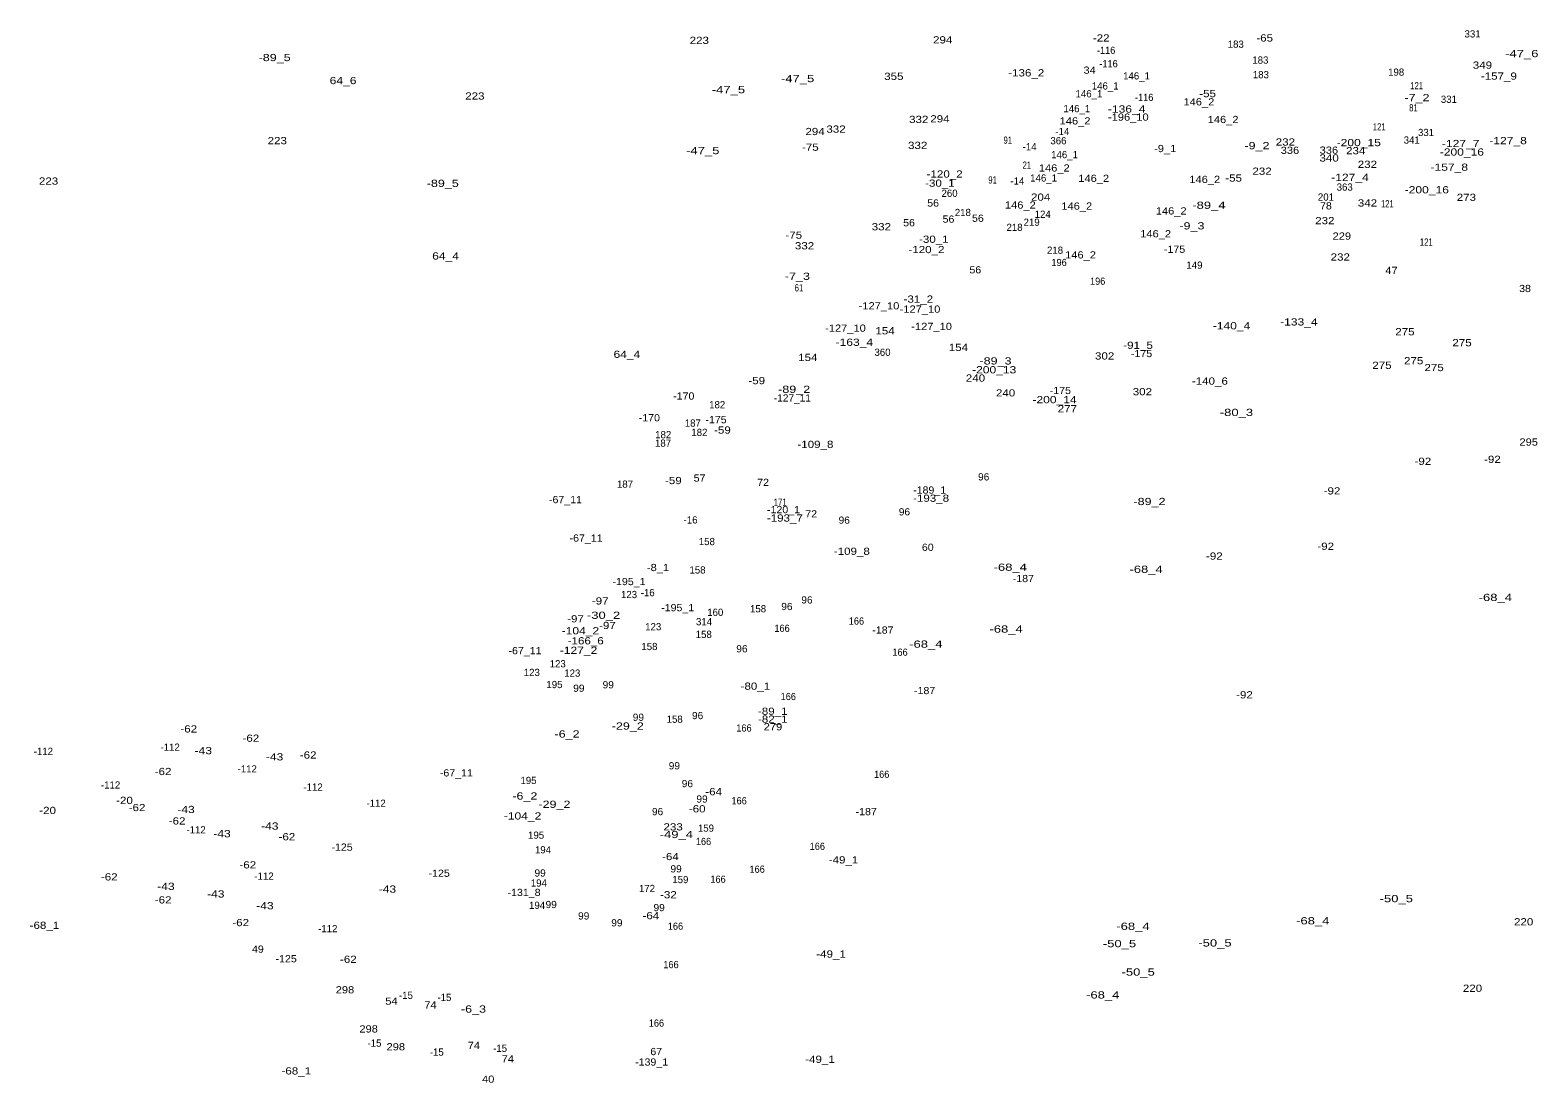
# Model space of a CAD drawing. Extents: x -662996 to -659766, y -998554 to -993949.
# Drawn here: x -661834 to -660997, y -995683 to -995099 of the extents above; entities that cross this region are included whole.
import ezdxf
from ezdxf.enums import TextEntityAlignment as Align

# ---------------------------------------------------------------- set-up
doc = ezdxf.new("R2010")
doc.units = 0
doc.header["$LTSCALE"] = 1.6
doc.layers.add('24', color=7, linetype='Continuous')

msp = doc.modelspace()

# ---------------------------------------------------------------- texts
at = {"layer": '24'}
for s, width, p in [('-22', 1.2, (-661239.28, -995105.72)), ('-65', 1.2, (-661148.56, -995105.71)), ('223', 1.2, (-661462.29, -995107.05)), ('294', 1.2, (-661327.24, -995106.76)), ('-116', 0.95, (-661236.54, -995112.58)), ('-47_6', 1.35, (-661005.9, -995114.38)), ('-89_5', 1.3, (-661697.94, -995116.57)), ('-116', 0.95, (-661235.21, -995120)), ('349', 1.2, (-661027.74, -995120.78)), ('64_6', 1.25, (-661659.97, -995129.36)), ('-47_5', 1.35, (-661407.74, -995128.25)), ('355', 1.2, (-661354.34, -995127)), ('-136_2', 1.2, (-661280.861, -995125.06)), ('34', 1.15, (-661245.709, -995123.58)), ('-157_9', 1.2, (-661018.62, -995126.87)), ('223', 1.2, (-661586.819, -995137.91)), ('-47_5', 1.35, (-661446.11, -995134.39)), ('-116', 0.95, (-661215.42, -995138.67)), ('-55', 1.2, (-661180.25, -995136.59)), ('-7_2', 1.3, (-661064.08, -995138.81)), ('121', 0.8, (-661064.25, -995132.18)), ('-136_4', 1.25, (-661225.15, -995145.14)), ('146_2', 1.15, (-661185.069, -995141.15)), ('81', 0.8, (-661065.98, -995144.45)), ('332', 1.2, (-661386.419, -995156.28)), ('332', 1.2, (-661340.53, -995150.9)), ('294', 1.2, (-661328.76, -995150.57)), ('146_2', 1.15, (-661253.799, -995151.72)), ('-196_10', 1.15, (-661224.23, -995149.6)), ('146_2', 1.15, (-661171.63, -995150.95)), ('121', 0.8, (-661084.98, -995155.04)), ('223', 1.2, (-661696.49, -995162.67)), ('294', 1.2, (-661398.07, -995157.62)), ('91', 0.8, (-661291.101, -995162.4)), ('232', 1.2, (-661137.069, -995163.43)), ('-200_15', 1.25, (-661096.36, -995163.76)), ('-127_7', 1.25, (-661039.78, -995164.27)), ('-127_8', 1.25, (-661013.5, -995162.65)), ('-47_5', 1.35, (-661460.35, -995168.2)), ('-75', 1.2, (-661400.671, -995166.3)), ('332', 1.2, (-661341.1, -995165.31)), ('-9_1', 1.15, (-661203.76, -995167.06)), ('-9_2', 1.3, (-661152.84, -995165.47)), ('336', 1.15, (-661134.55, -995168.04)), ('340', 1.2, (-661112.809, -995172.29)), ('336', 1.15, (-661112.95, -995167.95)), ('234', 1.2, (-661098.04, -995168.24)), ('-200_16', 1.25, (-661039.13, -995168.99)), ('-120_2', 1.2, (-661326.16, -995181.19)), ('21', 0.8, (-661280.54, -995176.26)), ('146_2', 1.15, (-661265.319, -995177.84)), ('232', 1.2, (-661150.02, -995179.62)), ('232', 1.2, (-661091.569, -995175.81)), ('-157_8', 1.25, (-661046.13, -995177.4)), ('223', 1.2, (-661823.38, -995185.11)), ('-89_5', 1.3, (-661604.65, -995186.37)), ('-30_1', 1.2, (-661328.79, -995186.26)), ('91', 0.8, (-661299.551, -995184.49)), ('146_2', 1.15, (-661243.429, -995183.6)), ('146_2', 1.15, (-661181.799, -995184.18)), ('-55', 1.2, (-661165.78, -995183.44)), ('-127_4', 1.25, (-661101.22, -995183.05)), ('-200_16', 1.25, (-661058.611, -995189.93)), ('56', 1.1, (-661332.56, -995197.27)), ('204', 1.2, (-661272.89, -995194.01)), ('342', 1.2, (-661091.53, -995197.24)), ('121', 0.8, (-661080.48, -995197.7)), ('273', 1.2, (-661036.64, -995194.14)), ('56', 1.1, (-661324.02, -995206.2)), ('56', 1.1, (-661307.7, -995205.72)), ('146_2', 1.15, (-661284.14, -995198.39)), ('146_2', 1.15, (-661252.84, -995198.97)), ('146_2', 1.15, (-661200.429, -995201.66)), ('-89_4', 1.35, (-661179.51, -995198.51)), ('78', 1.1, (-661114.58, -995198.85)), ('332', 1.2, (-661361.26, -995210.44)), ('56', 1.1, (-661345.91, -995208.22)), ('146_2', 1.15, (-661209.069, -995214.34)), ('-9_3', 1.3, (-661188.94, -995209.95)), ('232', 1.2, (-661115.179, -995207.05)), ('-75', 1.2, (-661409.88, -995215.09)), ('332', 1.2, (-661403.89, -995221.01)), ('-120_2', 1.2, (-661336.25, -995223.1)), ('-30_1', 1.2, (-661332.15, -995217.37)), ('-175', 1.1, (-661198.56, -995222.94)), ('229', 1.15, (-661105.75, -995215.62)), ('121', 0.8, (-661058.87, -995218.93)), ('64_4', 1.25, (-661603.07, -995226.66)), ('196', 0.95, (-661262.65, -995230.26)), ('146_2', 1.15, (-661250.73, -995226.05)), ('232', 1.2, (-661106.61, -995227.24)), ('-7_3', 1.3, (-661407.85, -995237.92)), ('56', 1.1, (-661309.14, -995234.34)), ('47', 1.15, (-661078.2, -995234.66)), ('61', 0.8, (-661407.01, -995244.35)), ('196', 0.95, (-661241.24, -995240.63)), ('38', 1.1, (-661004.1, -995244.7)), ('-127_10', 1.15, (-661362.571, -995254.31)), ('-127_10', 1.15, (-661339.821, -995256.14)), ('-31_2', 1.2, (-661340.73, -995250.58)), ('-133_4', 1.25, (-661129.59, -995263.24)), ('-127_10', 1.15, (-661381.191, -995266.69)), ('154 ', 1.2, (-661358.35, -995268.16)), ('-127_10', 1.15, (-661333.38, -995265.74)), ('-140_4', 1.25, (-661166.95, -995265.37)), ('275', 1.2, (-661070.74, -995268.67)), ('64_4', 1.25, (-661502.46, -995281.21)), ('-163_4', 1.25, (-661376.25, -995274.52)), ('154 ', 1.2, (-661317.64, -995277.38)), ('-91_5', 1.2, (-661218.811, -995276.2)), ('-175', 1.1, (-661216.89, -995280.79)), ('275', 1.2, (-661039.04, -995274.76)), ('154 ', 1.2, (-661401.17, -995282.95)), ('-200_13', 1.25, (-661298.66, -995289.79)), ('-89_3', 1.3, (-661297.93, -995284.88)), ('302', 1.2, (-661237.36, -995282.13)), ('275', 1.2, (-661083.5, -995287.33)), ('275', 1.2, (-661065.88, -995284.76)), ('275', 1.2, (-661054.55, -995288.57)), ('-59', 1.2, (-661430.42, -995295.81)), ('240', 1.2, (-661309.049, -995294.38)), ('-140_6', 1.2, (-661178.98, -995296.05)), ('-170', 1.1, (-661470.91, -995304.35)), ('-127_11', 1.05, (-661410.63, -995305.43)), ('-89_2', 1.3, (-661409.65, -995300.63)), ('240', 1.2, (-661292.34, -995302.62)), ('-200_14', 1.25, (-661265.16, -995306.36)), ('-175', 1.1, (-661261.94, -995301.29)), ('302', 1.2, (-661216.419, -995301.94)), ('277', 1.2, (-661258.081, -995311.43)), ('-80_3', 1.35, (-661164.23, -995313.45)), ('-170', 1.1, (-661490.01, -995316.41)), ('-175', 1.1, (-661453.02, -995317.47)), ('-59', 1.2, (-661449.46, -995323.24)), ('-109_8', 1.2, (-661397.87, -995331.19)), ('295', 1.15, (-661002.06, -995329.88)), ('-92', 1.2, (-661060.77, -995340.56)), ('-92', 1.2, (-661022.19, -995339.49)), ('-59', 1.2, (-661476.69, -995351.24)), ('57', 1.1, (-661462.14, -995349.87)), ('72', 1.1, (-661426.91, -995352.25)), ('-189_1', 1.1, (-661334.471, -995356.53)), ('96', 1.05, (-661304.49, -995349.2)), ('-92', 1.2, (-661111.2, -995356.99)), ('-67_11', 1.1, (-661536.54, -995361.81)), ('171', 0.8, (-661417.421, -995363.24)), ('-193_8', 1.2, (-661333.671, -995361.04)), ('-89_2', 1.3, (-661212.49, -995362.87)), ('-193_7', 1.2, (-661414.82, -995372.05)), ('-120_1', 1.1, (-661415.56, -995367.38)), ('72', 1.1, (-661400.22, -995369.73)), ('96', 1.05, (-661381.87, -995373.21)), ('96', 1.05, (-661348.46, -995368.6)), ('-67_11', 1.1, (-661525.11, -995383.14)), ('-109_8', 1.2, (-661377.66, -995390.49)), ('60', 1.1, (-661335.52, -995388.29)), ('-92', 1.2, (-661114.7, -995387.7)), ('-92', 1.2, (-661176.5, -995393.15)), ('-195_1', 1.1, (-661501.311, -995407.29)), ('-8_1', 1.15, (-661485.209, -995399.49)), ('-68_4', 1.35, (-661289.75, -995399.33)), ('-187', 1.1, (-661282.46, -995405.61)), ('-68_4', 1.35, (-661214.35, -995400.48)), ('-97', 1.2, (-661517.27, -995418.04)), ('-195_1', 1.1, (-661474.301, -995421.77)), ('96', 1.05, (-661413.68, -995421.12)), ('96', 1.05, (-661402.55, -995417.47)), ('-68_4', 1.35, (-661020.59, -995416.1)), ('-97', 1.2, (-661530.97, -995427.95)), ('-30_2', 1.35, (-661515.419, -995425.98)), ('-97', 1.2, (-661513.28, -995431.65)), ('166', 0.95, (-661375.1, -995429.19)), ('-104_2', 1.25, (-661528.25, -995434.56)), ('-166_6', 1.2, (-661525.329, -995440.15)), ('166', 0.95, (-661416.38, -995433.23)), ('-187', 1.1, (-661360.41, -995434.17)), ('-68_4', 1.35, (-661292.04, -995433.62)), ('-67_11', 1.1, (-661559, -995445.62)), ('-127_2', 1.25, (-661529.31, -995445.43)), ('96', 1.05, (-661438.64, -995444.56)), ('166', 0.95, (-661350.9, -995446.46)), ('-68_4', 1.35, (-661336.59, -995442)), ('99', 1.05, (-661512.81, -995464.54)), ('-80_1', 1.2, (-661431.169, -995465.32)), ('99', 1.05, (-661529.13, -995466.46)), ('166', 0.95, (-661412.92, -995471.06)), ('-187', 1.1, (-661337.26, -995467.76)), ('-92', 1.2, (-661159.79, -995470.13)), ('99', 1.05, (-661496.1, -995482.6)), ('96', 1.05, (-661463.22, -995481.63)), ('-89_1', 1.2, (-661421.551, -995479.24)), ('-62', 1.2, (-661745.59, -995489.04)), ('-29_2', 1.3, (-661501.99, -995487.44)), ('166', 0.95, (-661437.5, -995488.54)), ('-82_1', 1.2, (-661421.52, -995483.61)), ('279', 1.15, (-661421.41, -995487.83)), ('-62', 1.2, (-661711.13, -995494.19)), ('-6_2', 1.3, (-661535.68, -995491.85)), ('-43', 1.25, (-661737.51, -995501.08)), ('-43', 1.25, (-661697.96, -995504.54)), ('-62', 1.2, (-661679.33, -995503.52)), ('-62', 1.2, (-661759.85, -995512.66)), ('-67_11', 1.1, (-661597.09, -995513.43)), ('99', 1.05, (-661476.13, -995509.49)), ('166', 0.95, (-661361.08, -995514.23)), ('96', 1.05, (-661468.92, -995519.37)), ('-64', 1.2, (-661454.321, -995523.84)), ('-20', 1.2, (-661781.26, -995528.69)), ('-62', 1.2, (-661774.29, -995532.66)), ('-6_2', 1.3, (-661559.11, -995526.24)), ('-29_2', 1.3, (-661542.69, -995530.85)), ('99', 1.05, (-661460.78, -995527.93)), ('166', 0.95, (-661440.19, -995528.86)), ('-20', 1.2, (-661823.89, -995534.26)), ('-62', 1.2, (-661752.07, -995540.09)), ('-43', 1.25, (-661747.11, -995533.73)), ('-104_2', 1.25, (-661560.37, -995537.32)), ('96', 1.05, (-661485.44, -995534.92)), ('-60', 1.2, (-661463.46, -995533.37)), ('-187', 1.1, (-661369.67, -995534.92)), ('-43', 1.25, (-661727.14, -995547.18)), ('-43', 1.25, (-661700.64, -995542.95)), ('-62', 1.2, (-661691.13, -995548.85)), ('-49_4', 1.35, (-661475.049, -995547.61)), ('233', 1.2, (-661476.809, -995543.38)), ('-125', 1.1, (-661660.52, -995554.62)), ('166', 0.95, (-661459.96, -995551.47)), ('166', 0.95, (-661396.79, -995554.19)), ('-62', 1.2, (-661712.84, -995564.47)), ('-64', 1.2, (-661478.311, -995559.85)), ('-49_1', 1.2, (-661382.26, -995561.69)), ('-62', 1.2, (-661789.71, -995571.14)), ('-125', 1.1, (-661606.63, -995569.1)), ('99', 1.05, (-661550.63, -995568.97)), ('99', 1.05, (-661475.17, -995566.66)), ('166', 0.95, (-661451.9, -995572.43)), ('166', 0.95, (-661430.2, -995566.86)), ('-43', 1.25, (-661758.25, -995576.37)), ('-43', 1.25, (-661730.6, -995580.6)), ('-43', 1.25, (-661635.36, -995577.91)), ('-131_8', 1.1, (-661559.54, -995579.76)), ('-32', 1.2, (-661479.44, -995581.05)), ('-62', 1.2, (-661759.81, -995583.9)), ('-43', 1.25, (-661703.33, -995587.13)), ('99', 1.05, (-661544.49, -995586.45)), ('99', 1.05, (-661484.58, -995588.18)), ('-50_5', 1.35, (-661075.52, -995583.19)), ('-68_1', 1.2, (-661825.681, -995598)), ('-62', 1.2, (-661716.78, -995596.47)), ('99', 1.05, (-661526.44, -995592.79)), ('99', 1.05, (-661508.01, -995596.63)), ('-64', 1.2, (-661489.16, -995592.62)), ('166', 0.95, (-661475.52, -995598.47)), ('-68_4', 1.35, (-661221.66, -995598.53)), ('-68_4', 1.35, (-661121.89, -995595.48)), ('220', 1.2, (-661004.84, -995596.04)), ('-50_5', 1.35, (-661229.13, -995608.16)), ('-50_5', 1.35, (-661176.14, -995607.77)), ('49', 1.1, (-661707.24, -995611.21)), ('-125', 1.1, (-661691.551, -995616.52)), ('-49_1', 1.2, (-661389.17, -995613.93)), ('-62', 1.2, (-661657.05, -995616.85)), ('166', 0.95, (-661478.01, -995619.79)), ('-50_5', 1.35, (-661218.76, -995623.91)), ('220', 1.2, (-661033.25, -995632.91)), ('298', 1.15, (-661658.9, -995633.76)), ('54', 1.15, (-661633.12, -995640.06)), ('-68_4', 1.35, (-661238.42, -995636.62)), ('74', 1.15, (-661611.48, -995642.17)), ('-6_3', 1.3, (-661587.6, -995644.44)), ('298', 1.15, (-661645.77, -995655.47)), ('166', 0.95, (-661486.08, -995652.25)), ('298', 1.15, (-661630.72, -995665.38)), ('74', 1.15, (-661587.38, -995664.64)), ('74', 1.15, (-661568.56, -995672.1)), ('-139_1', 1.1, (-661488.74, -995673.84)), ('67', 1.1, (-661486.2, -995668.03)), ('-49_1', 1.2, (-661395.32, -995672.32)), ('-68_1', 1.2, (-661685.921, -995678.77)), ('40', 1.15, (-661579.439, -995683.34))]:
    msp.add_text(s, height=4, dxfattribs=dict(at, width=width)).set_placement(p, align=Align.CENTER)
for s, p in [('331', (-661033.199, -995103.45)), ('183', (-661164.59, -995109.16)), ('183', (-661150.959, -995117.99)), ('146_1', (-661219.679, -995126.76)), ('183', (-661150.669, -995126.06)), ('198', (-661075.611, -995124.67)), ('146_1', (-661246.079, -995136.65)), ('146_1', (-661237.049, -995132.33)), ('331', (-661046.35, -995139.71)), ('146_1', (-661252.799, -995144.91)), ('366', (-661263.008, -995162.71)), ('-14', (-661260.84, -995157.6)), ('341', (-661066.97, -995162.36)), ('331', (-661059.03, -995158.15)), ('-14', (-661278.99, -995166.05)), ('146_1', (-661259.61, -995170.43)), ('-14', (-661285.8, -995185.07)), ('146_1', (-661271.23, -995183.4)), ('363', (-661104.163, -995188.44)), ('260', (-661323.427, -995191.88)), ('201', (-661114.58, -995193.97)), ('218', (-661316.059, -995202.52)), ('124', (-661271.74, -995203.52)), ('218', (-661287.35, -995210.78)), ('219', (-661277.88, -995207.94)), ('218', (-661264.89, -995223.46)), ('149', (-661187.55, -995231.74)), ('360', (-661360.627, -995280.06)), ('182', (-661452.36, -995309.17)), ('187', (-661465.89, -995319.35)), ('187', (-661482.41, -995330.49)), ('182', (-661482.309, -995325.78)), ('182', (-661462.25, -995324.53)), ('187', (-661503.53, -995353.25)), ('-16', (-661467.12, -995373.09)), ('158', (-661458.1, -995385.09)), ('158', (-661463.29, -995400.84)), ('123', (-661501.28, -995414.48)), ('-16', (-661490.93, -995413.43)), ('158', (-661429.679, -995422.38)), ('123', (-661487.84, -995432.34)), ('314', (-661459.66, -995429.57)), ('160', (-661453.431, -995424.35)), ('158', (-661459.819, -995436.59)), ('158', (-661489.97, -995443.32)), ('123', (-661540.84, -995452.9)), ('123', (-661555.24, -995457.7)), ('195', (-661542.671, -995464.42)), ('123', (-661532.77, -995458.08)), ('158', (-661475.949, -995483.65)), ('-112', (-661755.921, -995499.16)), ('-112', (-661826.27, -995501.49)), ('-112', (-661713.16, -995511.22)), ('-112', (-661788.951, -995520.16)), ('-112', (-661676.63, -995521.32)), ('195', (-661557.071, -995517.63)), ('-112', (-661641.65, -995530.27)), ('-112', (-661741.541, -995545.04)), ('195', (-661552.851, -995547.97)), ('159', (-661458.601, -995544.08)), ('194', (-661549.03, -995556.1)), ('-112', (-661703.831, -995570.71)), ('194', (-661551.34, -995574.53)), ('159', (-661472.811, -995572.61)), ('172', (-661491.321, -995577.55)), ('194', (-661552.3, -995586.92)), ('-112', (-661668.461, -995599.87)), ('-15', (-661625.061, -995636.84)), ('-15', (-661603.75, -995638)), ('-15', (-661642.53, -995663.35)), ('-15', (-661572.841, -995666.23)), ('-15', (-661607.971, -995668.34))]:
    msp.add_text(s, height=4, dxfattribs=at).set_placement(p, align=Align.CENTER)

doc.saveas('drawing.dxf')
